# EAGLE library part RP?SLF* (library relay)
Special Load PCB Relay SCHRACK 1 pole 16 A, for high inrush currents, bistable Source: http://www.schrack.com/.. 5837.pdf
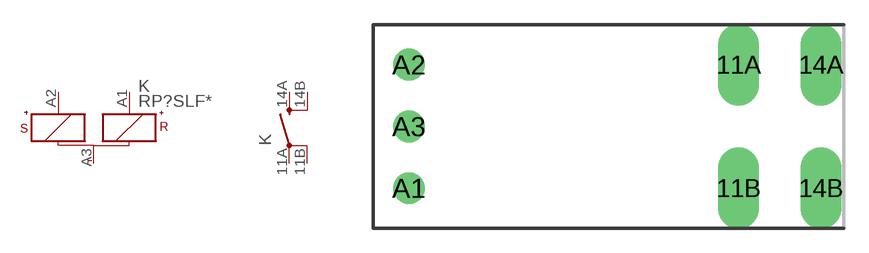
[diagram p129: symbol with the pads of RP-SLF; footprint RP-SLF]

Designator prefix K; gates 1=+KS+KR- 2=S-X2

## RP3SLF12 (MPN: RP3SLF12; OC_FARNELL: unknown; OC_NEWARK: 16R6258), RP3SLF24 (MF: TYCO ELECTRONICS; MPN: RP3SLF24; OC_FARNELL: unknown; OC_NEWARK: 08H3556)  [RP-SLF]
11A  2:PA  pas
11B  2:PB  pas
14A  2:SA  pas
14B  2:SB  pas
A1  1:R+  pas
A2  1:S+  pas
A3  1:-  pas

## RP7SLF12 (OC_FARNELL: unknown; OC_NEWARK: unknown), RP7SLF24 (OC_FARNELL: unknown; OC_NEWARK: unknown)  [RP-SLF]
Pads as for RP-SLF

## Footprint RP-SLF (pad centres in mm)
Special Load PCB Relay SCHRACK 1 pole 16 A, for high inrush currents, bistable Source: http://www.schrack.com/.. 5837.pdf
drill 1.3 pad 2.5 long: 11A 7.56,3.78; 11B 7.56,-3.78; 14A 12.6,3.78; 14B 12.6,-3.78
drill 1.3 round: A1 -12.6,-3.78; A2 -12.6,3.78; A3 -12.6,0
